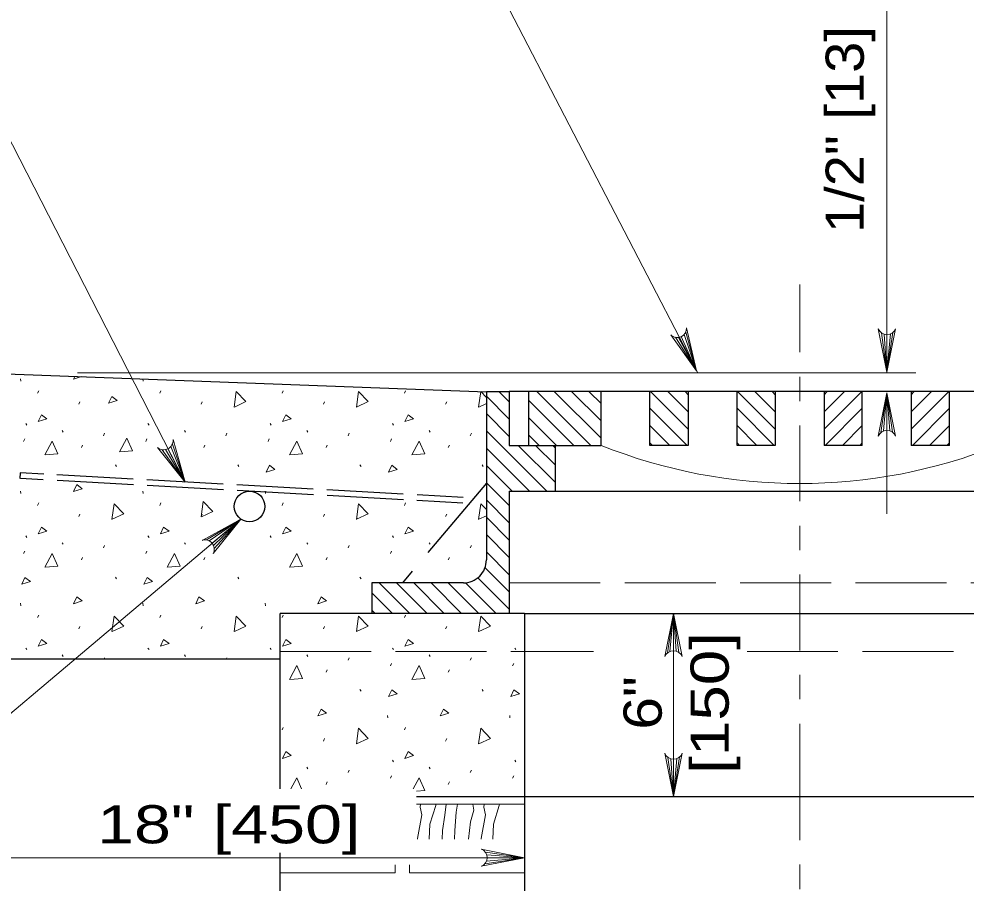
# Model space of a CAD drawing. Extents: x 1083.1 to 1117.1, y 719.4 to 763.4.
# Drawn here: x 1104.965 to 1108.838, y 732.781 to 736.318 of the extents above; entities that cross this region are included whole.
import ezdxf
from ezdxf.enums import TextEntityAlignment as Align

# ---------------------------------------------------------------- set-up
doc = ezdxf.new("R2010")
doc.units = 0
doc.header["$LTSCALE"] = 0.062
doc.linetypes.add('DOT_DASHED', pattern=[7.7, 5, -1.2, 0.3, -1.2])
doc.linetypes.add('LONG_DASHED', pattern=[7.5, 6, -1.5])
doc.layers.add('1', color=7, linetype='Continuous', lineweight=13)

msp = doc.modelspace()

# ---------------------------------------------------------------- linework, layer by layer
at = {"layer": '1'}
for p, q in [((1108.51433, 734.87242), (1108.51433, 736.79592)), ((1105.64367, 734.42225), (1104.71917, 736.23)), ((1107.68467, 735.02592), (1107.73533, 734.87758)), ((1107.69167, 735.03575), (1107.73533, 734.87758)), ((1108.49192, 735.03267), (1108.51433, 734.87242)), ((1108.503, 735.02725), (1108.51433, 734.87242)), ((1108.53917, 735.03458), (1108.51433, 734.87242)), ((1108.52875, 735.02842), (1108.51433, 734.87242)), ((1108.51433, 735.02558), (1108.51433, 734.87242)), ((1107.64933, 735.01475), (1107.73533, 734.87758)), ((1107.66167, 735.01433), (1107.73533, 734.87758)), ((1107.67267, 735.01742), (1107.73533, 734.87758)), ((1105.20442, 734.86992), (1108.6325, 734.86992)), ((1104.97158, 734.84508), (1104.97275, 734.83508)), ((1105.18758, 734.84342), (1105.19308, 734.85483)), ((1105.22092, 734.85383), (1105.18758, 734.84342)), ((1105.47158, 734.84467), (1105.47267, 734.83508)), ((1105.04083, 734.78617), (1105.04525, 734.79617)), ((1105.54075, 734.78617), (1105.54517, 734.79617)), ((1106.04075, 734.78617), (1106.04517, 734.79617)), ((1106.54075, 734.78617), (1106.54517, 734.79617)), ((1106.97008, 734.75042), (1106.92742, 734.79308)), ((1107.304, 734.5725), (1107.08425, 734.79233)), ((1107.34508, 734.60217), (1107.15492, 734.79233)), ((1107.34508, 734.67283), (1107.22558, 734.79233)), ((1107.34508, 734.74358), (1107.29633, 734.79233)), ((1107.70133, 734.63858), (1107.54867, 734.79125)), ((1107.70133, 734.70933), (1107.61942, 734.79125)), ((1107.70133, 734.78), (1107.69008, 734.79125)), ((1108.05758, 734.63858), (1107.90492, 734.79125)), ((1108.05758, 734.70933), (1107.97567, 734.79125)), ((1108.05758, 734.78), (1108.04633, 734.79125)), ((1108.25742, 734.78), (1108.26867, 734.79125)), ((1108.25742, 734.70933), (1108.33933, 734.79125)), ((1108.25742, 734.63858), (1108.41008, 734.79125)), ((1108.61367, 734.78), (1108.62492, 734.79125)), ((1108.61367, 734.70933), (1108.69558, 734.79125)), ((1108.61367, 734.63858), (1108.76633, 734.79125)), ((1105.2095, 734.74067), (1105.214, 734.75067)), ((1105.70942, 734.74067), (1105.71392, 734.75067)), ((1106.20942, 734.74067), (1106.21392, 734.75067)), ((1106.70942, 734.74067), (1106.71392, 734.75067)), ((1106.97008, 734.67967), (1106.87633, 734.77342)), ((1107.23325, 734.5725), (1107.04825, 734.75758)), ((1108.48958, 734.62525), (1108.51433, 734.7875)), ((1108.49992, 734.63142), (1108.51433, 734.7875)), ((1108.51433, 734.63425), (1108.51433, 734.7875)), ((1108.52567, 734.63258), (1108.51433, 734.7875)), ((1108.53675, 734.62717), (1108.51433, 734.7875)), ((1108.51433, 734.7875), (1108.51433, 734.29208)), ((1108.51433, 734.7875), (1108.51433, 734.29208)), ((1106.87633, 734.74383), (1106.8455, 734.72958)), ((1107.69675, 734.5725), (1107.54508, 734.72417)), ((1108.053, 734.5725), (1107.90133, 734.72417)), ((1108.262, 734.5725), (1108.41367, 734.72417)), ((1108.61825, 734.5725), (1108.76992, 734.72417)), ((1106.97008, 734.60892), (1106.87633, 734.70267)), ((1107.16258, 734.5725), (1107.04825, 734.68692)), ((1104.99208, 734.66192), (1104.99658, 734.65525)), ((1105.492, 734.66192), (1105.4965, 734.65525)), ((1105.992, 734.66192), (1105.9965, 734.65525)), ((1106.492, 734.66192), (1106.4965, 734.65525)), ((1107.626, 734.5725), (1107.54508, 734.65342)), ((1107.98225, 734.5725), (1107.90133, 734.65342)), ((1108.33275, 734.5725), (1108.41367, 734.65342)), ((1108.689, 734.5725), (1108.76992, 734.65342)), ((1104.98375, 734.58875), (1104.98817, 734.59875)), ((1105.14167, 734.63367), (1105.14608, 734.627)), ((1105.31058, 734.61192), (1105.315, 734.62192)), ((1105.48367, 734.58875), (1105.48808, 734.59875)), ((1105.64158, 734.63367), (1105.646, 734.627)), ((1105.8105, 734.61192), (1105.81492, 734.62192)), ((1105.98367, 734.58875), (1105.98808, 734.59875)), ((1106.14158, 734.63367), (1106.146, 734.627)), ((1106.3105, 734.61192), (1106.31492, 734.62192)), ((1106.48367, 734.58875), (1106.48808, 734.59875)), ((1106.64158, 734.63367), (1106.646, 734.627)), ((1106.8105, 734.61192), (1106.81492, 734.62192)), ((1107.12333, 734.38508), (1106.87633, 734.632)), ((1107.09192, 734.5725), (1107.04825, 734.61617)), ((1105.22067, 734.56325), (1105.22508, 734.57317)), ((1105.57408, 734.55875), (1105.64367, 734.42225)), ((1105.58558, 734.56783), (1105.64367, 734.42225)), ((1105.59208, 734.578), (1105.64367, 734.42225)), ((1105.72058, 734.56325), (1105.725, 734.57317)), ((1106.22058, 734.56325), (1106.225, 734.57317)), ((1106.72058, 734.56325), (1106.725, 734.57317)), ((1107.05258, 734.38508), (1106.87633, 734.56125)), ((1107.15758, 734.4215), (1107.0065, 734.5725)), ((1107.15758, 734.49225), (1107.07725, 734.5725)), ((1107.15758, 734.56292), (1107.14792, 734.5725)), ((1107.55533, 734.5725), (1107.54508, 734.58275)), ((1107.91158, 734.5725), (1107.90133, 734.58275)), ((1108.40342, 734.5725), (1108.41367, 734.58275)), ((1108.75967, 734.5725), (1108.76992, 734.58275)), ((1105.55092, 734.55483), (1105.64367, 734.42225)), ((1105.56325, 734.55508), (1105.64367, 734.42225)), ((1105.35942, 734.49225), (1105.36383, 734.48558)), ((1105.85933, 734.49225), (1105.86375, 734.48558)), ((1106.35933, 734.49225), (1106.36375, 734.48558)), ((1106.85933, 734.49225), (1106.86375, 734.48558)), ((1106.98183, 734.38508), (1106.87633, 734.49067)), ((1106.97008, 734.32625), (1106.87633, 734.41992)), ((1104.97158, 734.38575), (1104.97275, 734.37575)), ((1105.4715, 734.38575), (1105.47267, 734.37575)), ((1105.9715, 734.38575), (1105.97267, 734.37575)), ((1105.04083, 734.32683), (1105.04525, 734.33683)), ((1105.54075, 734.32683), (1105.54517, 734.33683)), ((1106.04075, 734.32683), (1106.04517, 734.33683)), ((1106.54075, 734.32683), (1106.54517, 734.33683)), ((1106.97008, 734.2555), (1106.87633, 734.34925)), ((1105.2095, 734.28133), (1105.214, 734.29133)), ((1105.70942, 734.28133), (1105.71392, 734.29133)), ((1106.20942, 734.28133), (1106.21392, 734.29133)), ((1106.70942, 734.28133), (1106.71392, 734.29133)), ((1105.73167, 734.18533), (1105.87192, 734.2705)), ((1105.743, 734.18133), (1105.87192, 734.2705)), ((1105.75442, 734.17208), (1105.87192, 734.2705)), ((1105.76042, 734.16242), (1105.87192, 734.2705)), ((1105.76342, 734.15042), (1105.87192, 734.2705)), ((1106.87633, 734.2845), (1106.8455, 734.27025)), ((1106.97008, 734.18475), (1106.87633, 734.2785)), ((1104.99208, 734.20258), (1104.99658, 734.19592)), ((1105.14167, 734.17433), (1105.14608, 734.16767)), ((1105.492, 734.20258), (1105.4965, 734.19592)), ((1105.64158, 734.17433), (1105.646, 734.16767)), ((1105.992, 734.20258), (1105.9965, 734.19592)), ((1106.14158, 734.17433), (1106.146, 734.16767)), ((1106.492, 734.20258), (1106.4965, 734.19592)), ((1106.64158, 734.17433), (1106.646, 734.16767)), ((1106.97008, 734.11408), (1106.87633, 734.20783)), ((1104.98375, 734.12942), (1104.98817, 734.13942)), ((1105.31058, 734.15258), (1105.315, 734.16258)), ((1105.48367, 734.12942), (1105.48808, 734.13942)), ((1106.3105, 734.15258), (1106.31492, 734.16258)), ((1106.48367, 734.12942), (1106.48808, 734.13942)), ((1106.8105, 734.15258), (1106.81492, 734.16258)), ((1106.97008, 734.04333), (1106.87633, 734.13708)), ((1105.22067, 734.10392), (1105.22508, 734.11383)), ((1105.72058, 734.10392), (1105.725, 734.11383)), ((1106.22058, 734.10392), (1106.225, 734.11383)), ((1106.72058, 734.10392), (1106.725, 734.11383)), ((1106.97008, 733.97275), (1106.87075, 734.072)), ((1105.35942, 734.03283), (1105.36383, 734.02617)), ((1105.85933, 734.03283), (1105.86375, 734.02617)), ((1106.35933, 734.03283), (1106.36375, 734.02617)), ((1106.97008, 733.902), (1106.84125, 734.03075)), ((1106.56267, 733.88517), (1106.43767, 734.01008)), ((1106.63342, 733.88517), (1106.50842, 734.01008)), ((1106.70408, 733.88517), (1106.57908, 734.01008)), ((1106.77483, 733.88517), (1106.64983, 734.01008)), ((1106.8455, 733.88517), (1106.7205, 734.01008)), ((1106.91625, 733.88517), (1106.79125, 734.01008)), ((1106.49192, 733.88517), (1106.40758, 733.9695)), ((1104.97158, 733.92642), (1104.97275, 733.91642)), ((1105.4715, 733.92642), (1105.47267, 733.91642)), ((1105.9715, 733.92642), (1105.97267, 733.91642)), ((1106.42125, 733.88517), (1106.40758, 733.89883)), ((1105.04083, 733.8675), (1105.04525, 733.8775)), ((1105.54075, 733.8675), (1105.54517, 733.8775)), ((1106.04075, 733.8675), (1106.04517, 733.8775)), ((1106.54075, 733.8675), (1106.54517, 733.8775)), ((1107.61658, 733.72292), (1107.64133, 733.88517)), ((1107.62692, 733.72908), (1107.64133, 733.88517)), ((1107.64133, 733.37317), (1107.64133, 733.88517)), ((1107.64133, 733.73192), (1107.64133, 733.88517)), ((1107.65267, 733.73025), (1107.64133, 733.88517)), ((1107.66375, 733.72483), (1107.64133, 733.88517)), ((1105.2095, 733.822), (1105.214, 733.832)), ((1105.70942, 733.822), (1105.71392, 733.832)), ((1106.20942, 733.822), (1106.21392, 733.832)), ((1106.70942, 733.822), (1106.71392, 733.832)), ((1104.99208, 733.74325), (1104.99658, 733.73658)), ((1105.492, 733.74325), (1105.4965, 733.73658)), ((1105.992, 733.74325), (1105.9965, 733.73658)), ((1106.492, 733.74325), (1106.4965, 733.73658)), ((1106.992, 733.74325), (1106.9965, 733.73658)), ((1105.14167, 733.715), (1105.14608, 733.70833)), ((1105.64158, 733.715), (1105.646, 733.70833)), ((1106.14158, 733.715), (1106.146, 733.70833)), ((1106.64158, 733.715), (1106.646, 733.70833)), ((1105.3125, 733.69767), (1105.315, 733.70325)), ((1105.81242, 733.69767), (1105.81492, 733.70325)), ((1106.3105, 733.69325), (1106.31492, 733.70325)), ((1106.48367, 733.67008), (1106.48808, 733.68008)), ((1106.8105, 733.69325), (1106.81492, 733.70325)), ((1106.98367, 733.67008), (1106.98808, 733.68008)), ((1106.22058, 733.64458), (1106.225, 733.65458)), ((1106.72058, 733.64458), (1106.725, 733.65458)), ((1106.35933, 733.5735), (1106.36375, 733.56683)), ((1106.85933, 733.5735), (1106.86375, 733.56683)), ((1106.4715, 733.467), (1106.47267, 733.45708)), ((1106.9715, 733.467), (1106.97267, 733.45708)), ((1106.04075, 733.40817), (1106.04517, 733.41817)), ((1106.54075, 733.40817), (1106.54517, 733.41817)), ((1106.20942, 733.36267), (1106.21392, 733.37267)), ((1106.70942, 733.36267), (1106.71392, 733.37267)), ((1107.64133, 733.37317), (1107.64133, 733.13525)), ((1106.492, 733.28392), (1106.4965, 733.27725)), ((1106.992, 733.28392), (1106.9965, 733.27725)), ((1107.61892, 733.29558), (1107.64133, 733.13525)), ((1107.63, 733.29017), (1107.64133, 733.13525)), ((1107.66617, 733.29742), (1107.64133, 733.13525)), ((1107.65575, 733.29133), (1107.64133, 733.13525)), ((1107.64133, 733.2885), (1107.64133, 733.13525)), ((1106.14158, 733.25567), (1106.146, 733.249)), ((1106.3105, 733.23392), (1106.31492, 733.24392)), ((1106.64158, 733.25567), (1106.646, 733.249)), ((1106.8105, 733.23392), (1106.81492, 733.24392)), ((1106.48367, 733.21075), (1106.48808, 733.22075)), ((1106.98367, 733.21075), (1106.98808, 733.22075)), ((1106.22058, 733.18525), (1106.225, 733.19525)), ((1106.72058, 733.18525), (1106.725, 733.19525)), ((1106.59033, 733.104), (1107.03508, 733.104)), ((1106.87233, 732.90775), (1107.03267, 732.88533)), ((1106.87775, 732.89667), (1107.03267, 732.88533)), ((1104.78267, 732.88533), (1105.99308, 732.88533)), ((1106.50308, 732.82283), (1106.50308, 732.85592)), ((1106.56208, 732.82283), (1106.56208, 732.85592)), ((1106.87042, 732.8605), (1107.03267, 732.88533)), ((1106.87658, 732.87092), (1107.03267, 732.88533)), ((1106.87942, 732.88533), (1107.03267, 732.88533)), ((1106.50308, 732.82283), (1106.03375, 732.82283)), ((1106.56208, 732.82283), (1107.03508, 732.82283))]:
    msp.add_line(p, q, dxfattribs=at)
at = {"layer": '1', "linetype": 'DOT_DASHED'}
for p, q in [((1108.1575, 733.12358), (1108.1575, 735.23117)), ((1108.1575, 728.68675), (1108.1575, 733.12358))]:
    msp.add_line(p, q, dxfattribs=at)
at = {"layer": '1', "lineweight": 25}
for p, q in [((1104.78267, 734.86992), (1106.87633, 734.79125)), ((1106.87633, 734.79308), (1106.87633, 734.10383)), ((1109.43867, 734.79217), (1106.97008, 734.79308)), ((1107.04825, 734.79225), (1107.04825, 734.5725)), ((1107.54508, 734.5725), (1107.54508, 734.79125)), ((1107.70133, 734.79125), (1107.70133, 734.5725)), ((1107.90133, 734.5725), (1107.90133, 734.79125)), ((1108.05758, 734.79125), (1108.05758, 734.5725)), ((1108.25742, 734.79125), (1108.25742, 734.5725)), ((1108.41367, 734.5725), (1108.41367, 734.79125)), ((1108.61367, 734.79125), (1108.61367, 734.5725)), ((1108.76992, 734.5725), (1108.76992, 734.79125)), ((1107.70133, 734.5725), (1107.54508, 734.5725)), ((1108.05758, 734.5725), (1107.90133, 734.5725)), ((1108.41367, 734.5725), (1108.25742, 734.5725)), ((1108.76992, 734.5725), (1108.61367, 734.5725)), ((1106.97008, 734.38508), (1106.97008, 733.88517)), ((1106.97008, 734.38508), (1109.34492, 734.38508)), ((1106.40758, 734.01008), (1106.40758, 733.88517)), ((1106.78258, 734.01008), (1106.40758, 734.01008)), ((1107.03258, 733.88517), (1106.03258, 733.88517)), ((1106.03258, 733.16725), (1106.03258, 733.88517)), ((1107.03258, 733.88517), (1110.28242, 733.88517)), ((1107.03258, 733.88517), (1107.03258, 732.96467)), ((1106.59033, 733.13525), (1108.96575, 733.13525)), ((1107.03258, 732.96467), (1107.03258, 730.75967)), ((1106.03258, 732.8195), (1106.03258, 732.90492)), ((1106.03258, 728.79217), (1106.03258, 732.8195))]:
    msp.add_line(p, q, dxfattribs=at)
at = {"layer": '1', "linetype": 'LONG_DASHED', "lineweight": 25}
for p, q in [((1105.06567, 734.45433), (1104.96933, 734.45967)), ((1104.96933, 734.43683), (1104.97067, 734.45967)), ((1105.43192, 734.434), (1105.11992, 734.45133)), ((1105.06425, 734.43158), (1104.97067, 734.43683)), ((1105.43333, 734.41108), (1105.12142, 734.42842)), ((1105.79967, 734.41358), (1105.48767, 734.43092)), ((1105.80108, 734.39067), (1105.48917, 734.408)), ((1106.16742, 734.39317), (1105.85533, 734.4105)), ((1106.87633, 734.41817), (1106.53258, 734.01008)), ((1106.16892, 734.37025), (1105.85683, 734.38758)), ((1106.53525, 734.37275), (1106.22317, 734.39008)), ((1106.53667, 734.34983), (1106.22467, 734.36717)), ((1106.78083, 734.35917), (1106.59367, 734.36958)), ((1106.77958, 734.33625), (1106.59242, 734.34667))]:
    msp.add_line(p, q, dxfattribs=at)
at = {"layer": '1', "linetype": 'LONG_DASHED'}
for p, q in [((1106.97008, 734.01008), (1109.34492, 734.01008)), ((1106.03258, 733.72892), (1107.31483, 733.72892)), ((1107.94217, 733.72892), (1110.28242, 733.72892))]:
    msp.add_line(p, q, dxfattribs=at)
at = {"layer": '1'}
for points in [[(1107.74158, 734.86992), (1106.68875, 736.90042), (1106.1915, 736.90042)], [(1107.69525, 735.05367), (1107.73533, 734.87758), (1107.63058, 735.02475)], [(1108.54975, 735.0495), (1108.51433, 734.87242), (1108.47892, 735.0495)], [(1105.8445, 734.72917), (1105.85333, 734.79267), (1105.89308, 734.75158), (1105.8455, 734.72958)], [(1106.3445, 734.72917), (1106.35333, 734.79267), (1106.39308, 734.75158), (1106.3455, 734.72958)], [(1106.8445, 734.72917), (1106.85333, 734.79267), (1106.87633, 734.76892)], [(1108.47892, 734.61042), (1108.51433, 734.7875), (1108.54975, 734.61042)], [(1105.3755, 734.54583), (1105.4055, 734.60242), (1105.42883, 734.55025), (1105.37667, 734.54583)], [(1105.59483, 734.59608), (1105.64367, 734.42225), (1105.53167, 734.56392)], [(1105.07075, 734.53325), (1105.10075, 734.58983), (1105.12408, 734.53775), (1105.07192, 734.53325)], [(1106.07067, 734.53325), (1106.10067, 734.58983), (1106.124, 734.53775), (1106.07183, 734.53325)], [(1106.57067, 734.53325), (1106.60067, 734.58983), (1106.624, 734.53775), (1106.57183, 734.53325)], [(1105.34458, 734.26983), (1105.35342, 734.33333), (1105.39308, 734.29225), (1105.34558, 734.27025)], [(1105.70958, 734.27975), (1105.71842, 734.34325), (1105.75817, 734.30217), (1105.71058, 734.28017)], [(1106.3445, 734.26983), (1106.35333, 734.33333), (1106.39308, 734.29225), (1106.3455, 734.27025)], [(1106.8445, 734.26983), (1106.85333, 734.33333), (1106.87633, 734.30958)], [(1105.87192, 734.2705), (1104.13008, 732.8005), (1103.86075, 732.8005)], [(1105.71342, 734.18392), (1105.87192, 734.2705), (1105.75892, 734.12967)], [(1105.07075, 734.07392), (1105.10075, 734.1305), (1105.12408, 734.07833), (1105.07192, 734.07392)], [(1105.57067, 734.07392), (1105.60067, 734.1305), (1105.624, 734.07833), (1105.57183, 734.07392)], [(1106.07067, 734.07392), (1106.10067, 734.1305), (1106.124, 734.07833), (1106.07183, 734.07392)], [(1105.34458, 733.81058), (1105.35342, 733.874), (1105.39308, 733.83292), (1105.34558, 733.81092)], [(1105.8445, 733.81058), (1105.85333, 733.874), (1105.89308, 733.83292), (1105.8455, 733.81092)], [(1106.3445, 733.81058), (1106.35333, 733.874), (1106.39308, 733.83292), (1106.3455, 733.81092)], [(1106.8445, 733.81058), (1106.85333, 733.874), (1106.89308, 733.83292), (1106.8455, 733.81092)], [(1107.60592, 733.70808), (1107.64133, 733.88517), (1107.67675, 733.70808)], [(1106.07067, 733.61458), (1106.10067, 733.67117), (1106.124, 733.619), (1106.07183, 733.61458)], [(1106.57067, 733.61458), (1106.60067, 733.67117), (1106.624, 733.619), (1106.57183, 733.61458)], [(1106.3445, 733.35125), (1106.35333, 733.41467), (1106.39308, 733.37358), (1106.3455, 733.35158)], [(1106.8445, 733.35125), (1106.85333, 733.41467), (1106.89308, 733.37358), (1106.8455, 733.35158)], [(1107.67675, 733.31233), (1107.64133, 733.13525), (1107.60592, 733.31233)], [(1106.077, 733.16725), (1106.10067, 733.21183), (1106.12067, 733.16725)], [(1106.577, 733.16725), (1106.60067, 733.21183), (1106.624, 733.15967), (1106.59033, 733.15683)], [(1106.59517, 732.96108), (1106.59475, 732.96442), (1106.612, 733.06058), (1106.6055, 733.09208), (1106.60692, 733.104)], [(1106.66933, 733.104), (1106.669, 733.09833), (1106.64475, 733.02233), (1106.6425, 732.96108)], [(1106.69475, 732.96108), (1106.69667, 732.99633), (1106.70683, 733.05992), (1106.71208, 733.104)], [(1106.74542, 732.96108), (1106.74742, 732.99633), (1106.75208, 733.07108), (1106.758, 733.104)], [(1106.80333, 732.96108), (1106.81158, 733.03183), (1106.8245, 733.07992), (1106.82083, 733.104)], [(1106.85517, 732.96108), (1106.85475, 732.96442), (1106.872, 733.06058), (1106.8655, 733.09208), (1106.86692, 733.104)], [(1106.92933, 733.104), (1106.929, 733.09833), (1106.90475, 733.02233), (1106.9025, 732.96108)], [(1106.85558, 732.84992), (1107.03267, 732.88533), (1106.85558, 732.92067)], [(1105.99308, 732.88533), (1106.53725, 732.88533), (1107.03267, 732.88533)]]:
    msp.add_lwpolyline(points, dxfattribs=at)
at = {"layer": '1', "lineweight": 25}
for points in [[(1106.87633, 734.79308), (1106.97008, 734.79308), (1106.97008, 734.5725), (1107.15758, 734.5725), (1107.15758, 734.38508)], [(1107.04825, 734.5725), (1107.34508, 734.5725), (1107.34508, 734.79233)], [(1106.03258, 733.69767), (1105.97908, 733.69767), (1104.78267, 733.69767), (1104.44383, 733.69767), (1103.53283, 733.69767)]]:
    msp.add_lwpolyline(points, dxfattribs=at)
at = {"layer": '1'}
for points in [[(1105.3305, 734.74508), (1105.34383, 734.77283), (1105.36608, 734.75617)], [(1105.043, 734.66967), (1105.05633, 734.69742), (1105.07858, 734.68075)], [(1106.04292, 734.66967), (1106.05625, 734.69742), (1106.0785, 734.68075)], [(1106.54292, 734.66967), (1106.55625, 734.69742), (1106.5785, 734.68075)], [(1105.97583, 734.46342), (1105.98917, 734.49117), (1106.01142, 734.4745)], [(1106.47583, 734.46342), (1106.48917, 734.49117), (1106.51142, 734.4745)], [(1105.18758, 734.38408), (1105.20092, 734.41183), (1105.22308, 734.39517)], [(1105.043, 734.21033), (1105.05633, 734.23808), (1105.07858, 734.22142)], [(1105.54292, 734.21033), (1105.55625, 734.23808), (1105.5785, 734.22142)], [(1106.04292, 734.21033), (1106.05625, 734.23808), (1106.0785, 734.22142)], [(1106.54292, 734.21033), (1106.55625, 734.23808), (1106.5785, 734.22142)], [(1104.97592, 734.004), (1104.98925, 734.03175), (1105.0115, 734.01508)], [(1105.47583, 734.004), (1105.48917, 734.03175), (1105.51142, 734.01508)], [(1105.18758, 733.92475), (1105.20092, 733.9525), (1105.22308, 733.93583)], [(1105.6875, 733.92475), (1105.70083, 733.9525), (1105.723, 733.93583)], [(1106.1875, 733.92475), (1106.20083, 733.9525), (1106.223, 733.93583)], [(1105.043, 733.751), (1105.05633, 733.77875), (1105.07858, 733.76208)], [(1105.54292, 733.751), (1105.55625, 733.77875), (1105.5785, 733.76208)], [(1106.04292, 733.751), (1106.05625, 733.77875), (1106.0785, 733.76208)], [(1106.54292, 733.751), (1106.55625, 733.77875), (1106.5785, 733.76208)], [(1106.47583, 733.54467), (1106.48917, 733.57242), (1106.51142, 733.55575)], [(1106.97583, 733.54467), (1106.98917, 733.57242), (1107.01142, 733.55575)], [(1106.1875, 733.46533), (1106.20083, 733.49308), (1106.223, 733.47642)], [(1106.6875, 733.46533), (1106.70083, 733.49308), (1106.723, 733.47642)], [(1106.04292, 733.29167), (1106.05625, 733.31942), (1106.0785, 733.30275)], [(1106.54292, 733.29167), (1106.55625, 733.31942), (1106.5785, 733.30275)]]:
    msp.add_lwpolyline(points, close=True, dxfattribs=at)
for centre, start, end in [((1107.65705, 735.05225), 226.21185, 2.03798), ((1108.51431, 735.06377), 202.08782, 337.91395), ((1108.51439, 734.5961), 22.08782, 157.91395), ((1105.55672, 734.59269), 229.1078, 4.93392), ((1105.72522, 734.14759), 332.04632, 107.87245), ((1107.64139, 733.69377), 22.08782, 157.91395), ((1107.64131, 733.32663), 202.08782, 337.91395), ((1106.84125, 732.88533), 292.08605, 67.91218)]:
    msp.add_arc(centre, 0.03822, start, end, dxfattribs=at)
msp.add_ellipse((1108.15749, 736.60617), major_axis=(-2.19009, 0), ratio=0.999895, start_param=1.1907817, end_param=1.9508109, dxfattribs=at)
at = {"layer": '1', "lineweight": 25}
msp.add_ellipse((1105.9076, 734.32257), major_axis=(0.0625, 0), ratio=0.999895, dxfattribs=at)
msp.add_ellipse((1106.78256, 734.10386), major_axis=(-0.09375, 0), ratio=0.999895, start_param=1.5707963, end_param=3.1415927, dxfattribs=at)

# ---------------------------------------------------------------- texts
at = {"layer": '1'}
for s, width, p in [('1/2" [13]', 1.1, (1108.41967, 735.86487)), ('[150]', 1.25, (1107.86725, 733.51858)), ('6"', 1.15, (1107.59317, 733.51858))]:
    msp.add_text(s, height=0.156, rotation=90, dxfattribs=dict(at, width=width)).set_placement(p, align=Align.CENTER)
at = {"layer": '1', "width": 1.3}
msp.add_text('18" [450]', height=0.156, dxfattribs=at).set_placement((1105.82254, 732.944), align=Align.CENTER)

doc.saveas('drawing.dxf')
